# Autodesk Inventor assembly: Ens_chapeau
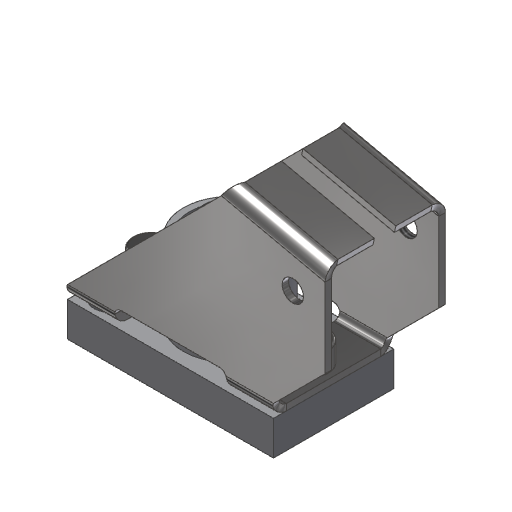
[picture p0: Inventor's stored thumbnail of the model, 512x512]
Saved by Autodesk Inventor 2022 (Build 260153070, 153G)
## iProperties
Created: 2018-06
Part Number: Ens_chapeau
Material: Générique
Document SubType Name: Assembly
Designer: Fabian Perrée
Mass: 105.136 g
Surface Area: 173.547 cm^2
Volume: 19.7524 cm^3
Density: 5.32267 g/cm^3
Author: Fabian Perrée
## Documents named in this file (5)
- C:\Users\Fabian\Google Drive\01_Giup\01_Clients\07_ENI\Manuscrit\Fichiers_exercice\Capteur\Ens_chapeau\Ens_chapeau.iam
- C:\Users\Fabian\Google Drive\01_Giup\01_Clients\07_ENI\Manuscrit\Fichiers_exercice\Capteur\Ens_chapeau\Composants\Chapeau_capteur.ipt
- C:\Users\Fabian\Google Drive\01_Giup\01_Clients\07_ENI\Manuscrit\Fichiers_exercice\Capteur\Ens_chapeau\Composants\Bille_18.ipt
- C:\Users\Fabian\Google Drive\01_Giup\01_Clients\07_ENI\Manuscrit\Fichiers_exercice\Capteur\Ens_levier\Composants\Etrier_tole.ipt
- C:\Users\Fabian\Google Drive\01_Giup\01_Clients\07_ENI\Manuscrit\Fichiers_exercice\CC\fr-FR\ISO 4762(2)\ISO 4762 - M5 x 8ISO.ipt
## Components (5 placed, 4 different names)
1. Etrier_tole:1 — Logement:3, Logement:4
2. Chapeau_capteur:1 — Logement:3, Logement:4
3. Bille_18:1
4. ISO 4762 M5 x 8:1
5. ISO 4762 M5 x 8:2
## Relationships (2: Insert 2)
- Logement:3 [Insert]: Etrier_tole:1 ↔ Chapeau_capteur:1
- Logement:4 [Insert]: Etrier_tole:1 ↔ Chapeau_capteur:1
